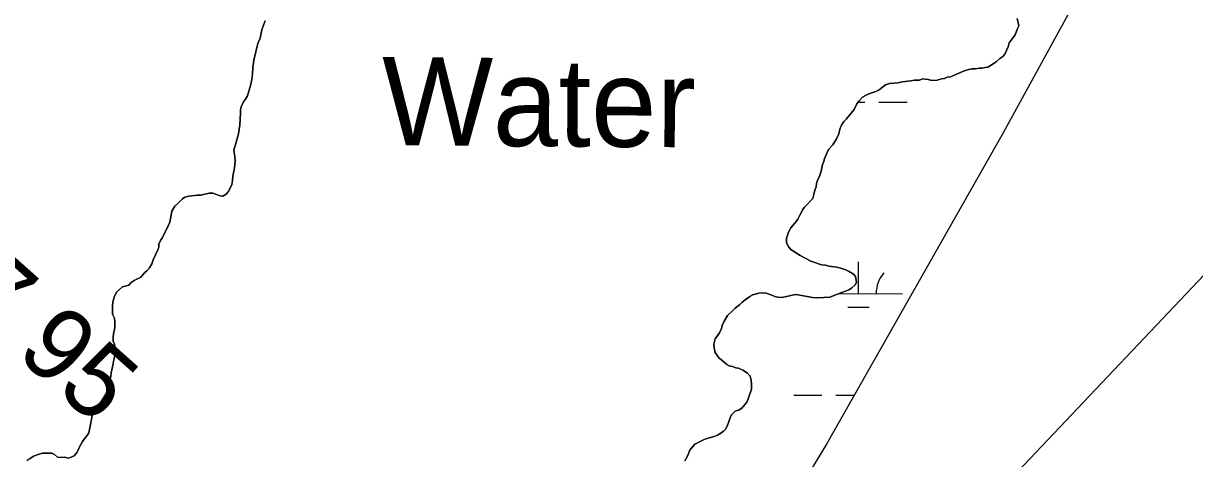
# Model space of a CAD drawing. Extents: x 3172297 to 3210190, y 958463 to 983887.
# Drawn here: x 3192826 to 3194156, y 965801 to 966296 of the extents above; entities that cross this region are included whole.
import ezdxf

# ---------------------------------------------------------------- set-up
doc = ezdxf.new("R2010")
doc.units = 0
for name, color, linetype in [('V-RIVR-IDEN', 7, 'Continuous'), ('V-RIVR-RANG-IDEN', 7, 'Continuous'), ('V-SITE-VEGE', 7, 'Continuous'), ('V-TOPO-MINR', 7, 'Continuous'), ('V-TOPO-SHOR', 7, 'Continuous'), ('V-WETL-SWMP', 7, 'Continuous')]:
    doc.layers.add(name, color=color, linetype=linetype)

msp = doc.modelspace()

# ---------------------------------------------------------------- linework, layer by layer
at = {"layer": 'V-SITE-VEGE'}
for p, q in [((3193098.4, 966293.5), (3193100.5, 966298.7)), ((3193955, 966301.1), (3193956.8, 966292.8)), ((3193095.4, 966282.8), (3193096.7, 966288.3)), ((3193096.7, 966288.3), (3193098.4, 966293.5)), ((3193955.1, 966289.7), (3193952.7, 966282.8)), ((3193956.8, 966292.8), (3193955.1, 966289.7)), ((3193087.5, 966253.8), (3193091.9, 966272.8)), ((3193091.9, 966272.8), (3193094.7, 966278.7)), ((3193094.7, 966278.7), (3193095.4, 966282.8)), ((3193945.8, 966273.5), (3193944.5, 966269)), ((3193952.7, 966282.8), (3193945.8, 966273.5)), ((3193941, 966260.8), (3193938.6, 966258)), ((3193944.5, 966269), (3193941, 966260.8)), ((3193085.9, 966238), (3193086.2, 966245.6)), ((3193086.2, 966245.6), (3193086.9, 966250.7)), ((3193086.9, 966250.7), (3193087.5, 966253.8)), ((3193918.4, 966245.5), (3193914.9, 966244.8)), ((3193921.5, 966245.9), (3193918.4, 966245.5)), ((3193927.6, 966249.7), (3193921.5, 966245.9)), ((3193931.1, 966252.1), (3193927.6, 966249.7)), ((3193935.2, 966255.6), (3193931.1, 966252.1)), ((3193938.6, 966258), (3193935.2, 966255.6)), ((3193083.8, 966225.2), (3193085.2, 966232.1)), ((3193085.2, 966232.1), (3193085.9, 966238)), ((3193847.1, 966232.5), (3193843.7, 966231.2)), ((3193853.6, 966231.9), (3193847.1, 966232.5)), ((3193857.8, 966230.9), (3193853.6, 966231.9)), ((3193868.8, 966232.6), (3193864, 966231.2)), ((3193872.2, 966233), (3193868.8, 966232.6)), ((3193875.3, 966234.4), (3193872.2, 966233)), ((3193879.1, 966235.1), (3193875.3, 966234.4)), ((3193893.9, 966241.3), (3193879.1, 966235.1)), ((3193898.4, 966243), (3193893.9, 966241.3)), ((3193903.5, 966244.1), (3193898.4, 966243)), ((3193907.7, 966244.1), (3193903.5, 966244.1)), ((3193911.8, 966244.8), (3193907.7, 966244.1)), ((3193914.9, 966244.8), (3193911.8, 966244.8)), ((3193080.1, 966213.5), (3193083.8, 966225.2)), ((3193797.9, 966220.3), (3193794.4, 966218.3)), ((3193805.4, 966225.9), (3193797.9, 966220.3)), ((3193809.6, 966227.3), (3193805.4, 966225.9)), ((3193819.6, 966228.3), (3193809.6, 966227.3)), ((3193824, 966229.4), (3193819.6, 966228.3)), ((3193834, 966230.4), (3193824, 966229.4)), ((3193838.1, 966231.1), (3193834, 966230.4)), ((3193843.7, 966231.2), (3193838.1, 966231.1)), ((3193864, 966231.2), (3193857.8, 966230.9)), ((3193073.2, 966200.8), (3193075.6, 966206.6)), ((3193075.6, 966206.6), (3193078, 966209.7)), ((3193078, 966209.7), (3193080.1, 966213.5)), ((3193774.8, 966207.5), (3193772.4, 966203.4)), ((3193779, 966211.7), (3193774.8, 966207.5)), ((3193782.4, 966213.7), (3193779, 966211.7)), ((3193786.2, 966215.5), (3193782.4, 966213.7)), ((3193794.4, 966218.3), (3193786.2, 966215.5)), ((3193071.6, 966180.1), (3193072.2, 966194.2)), ((3193072.2, 966197.3), (3193073.2, 966200.8)), ((3193072.2, 966194.2), (3193072.2, 966197.3)), ((3193769.7, 966197.8), (3193760.8, 966187.1)), ((3193772.4, 966203.4), (3193769.7, 966197.8)), ((3193069.9, 966170.4), (3193071.6, 966180.1)), ((3193755.3, 966179.9), (3193753.2, 966175.4)), ((3193758, 966184.4), (3193755.3, 966179.9)), ((3193760.8, 966187.1), (3193758, 966184.4)), ((3193067.5, 966160.8), (3193069.9, 966170.4)), ((3193752.2, 966170.2), (3193749.5, 966164.4)), ((3193753.2, 966175.4), (3193752.2, 966170.2)), ((3193064.8, 966151.5), (3193067.5, 966160.8)), ((3193740.6, 966152.6), (3193735.8, 966142.3)), ((3193745.4, 966157.8), (3193740.6, 966152.6)), ((3193749.5, 966164.4), (3193745.4, 966157.8)), ((3193065.8, 966144.2), (3193064.8, 966151.5)), ((3193065.5, 966131.8), (3193066.2, 966139.4)), ((3193066.2, 966139.4), (3193065.8, 966144.2)), ((3193735.1, 966138.8), (3193733.7, 966135.4)), ((3193735.8, 966142.3), (3193735.1, 966138.8)), ((3193063.5, 966122.2), (3193065.5, 966131.8)), ((3193732, 966127.8), (3193729.7, 966120.9)), ((3193733.7, 966135.4), (3193732, 966127.8)), ((3193058.7, 966104.6), (3193062.5, 966112.5)), ((3193062.5, 966112.5), (3193063.2, 966117.4)), ((3193063.2, 966117.4), (3193063.5, 966122.2)), ((3193726.9, 966114), (3193726.3, 966109.9)), ((3193728.3, 966118.2), (3193726.9, 966114)), ((3193729.7, 966120.9), (3193728.3, 966118.2)), ((3193009.2, 966098.2), (3193013.6, 966099.3)), ((3193013.6, 966099.3), (3193022.9, 966100.4)), ((3193022.9, 966100.4), (3193027.4, 966100.7)), ((3193027.4, 966100.7), (3193036.7, 966102.8)), ((3193036.7, 966102.8), (3193040.8, 966102.8)), ((3193040.8, 966102.8), (3193049.1, 966099.8)), ((3193049.1, 966099.8), (3193052.2, 966099.4)), ((3193052.2, 966099.4), (3193056, 966101.8)), ((3193056, 966101.8), (3193058.7, 966104.6)), ((3193723.9, 966101.3), (3193722.5, 966096.8)), ((3193724.9, 966106.1), (3193723.9, 966101.3)), ((3193726.3, 966109.9), (3193724.9, 966106.1)), ((3192994.4, 966082.4), (3192997.8, 966088.2)), ((3192997.8, 966088.2), (3193002.3, 966092.4)), ((3193002.3, 966092.4), (3193006.4, 966096.5)), ((3193006.4, 966096.5), (3193009.2, 966098.2)), ((3193713.2, 966086.8), (3193711.2, 966084.3)), ((3193722.5, 966096.8), (3193713.2, 966086.8)), ((3192992, 966069.9), (3192993, 966075.8)), ((3192993, 966075.8), (3192994.4, 966082.4)), ((3193705.7, 966073.3), (3193703.6, 966070.5)), ((3193707.8, 966077.8), (3193705.7, 966073.3)), ((3193711.2, 966084.3), (3193707.8, 966077.8)), ((3192983.5, 966052.4), (3192986.6, 966058.9)), ((3192986.6, 966058.9), (3192988.6, 966062.4)), ((3192988.6, 966062.4), (3192990.3, 966065.8)), ((3192990.3, 966065.8), (3192992, 966069.9)), ((3193697.5, 966063.3), (3193695.1, 966058.5)), ((3193703.6, 966070.5), (3193697.5, 966063.3)), ((3192979.7, 966044.8), (3192981.4, 966049.2)), ((3192981.4, 966049.2), (3192983.5, 966052.4)), ((3193693.7, 966055), (3193692.7, 966051.6)), ((3193692.7, 966051.6), (3193692.7, 966046.4)), ((3193692.7, 966046.4), (3193695.5, 966041.6)), ((3193695.1, 966058.5), (3193693.7, 966055)), ((3192973.2, 966027.2), (3192978.4, 966038.6)), ((3192978.4, 966038.6), (3192979.4, 966041.7)), ((3192979.4, 966041.7), (3192979.7, 966044.8)), ((3193695.5, 966041.6), (3193697.5, 966038.8)), ((3193697.5, 966038.8), (3193702, 966036.1)), ((3193702, 966036.1), (3193708.2, 966032)), ((3192969.1, 966018.2), (3192971.5, 966022.7)), ((3192971.5, 966022.7), (3192973.2, 966027.2)), ((3193708.2, 966032), (3193720.3, 966025.8)), ((3193720.3, 966025.8), (3193723.8, 966024.4)), ((3193723.8, 966024.4), (3193732.7, 966021.4)), ((3193732.7, 966021.4), (3193736.9, 966021)), ((3193736.9, 966021), (3193741, 966020)), ((3193741, 966020), (3193750, 966018.7)), ((3192954.7, 966005.1), (3192958.5, 966007.1)), ((3192958.5, 966007.1), (3192960.9, 966009.9)), ((3192960.9, 966009.9), (3192963.6, 966012.7)), ((3192963.6, 966012.7), (3192966, 966014.8)), ((3192966, 966014.8), (3192969.1, 966018.2)), ((3193750, 966018.7), (3193755.8, 966017.3)), ((3193755.8, 966017.3), (3193760.3, 966015.6)), ((3193760.3, 966015.6), (3193763.1, 966014.2)), ((3193763.1, 966014.2), (3193768.9, 966010.8)), ((3193768.9, 966010.8), (3193771, 966008.1)), ((3193771, 966008.1), (3193772.4, 966001.9)), ((3192931.7, 965990.9), (3192938.2, 965996.4)), ((3192938.2, 965996.4), (3192941.3, 965997.1)), ((3192941.3, 965997.1), (3192945.4, 965998.5)), ((3192945.4, 965998.5), (3192948.2, 966001.3)), ((3192948.2, 966001.3), (3192951.6, 966003.7)), ((3192951.6, 966003.7), (3192954.7, 966005.1)), ((3193763.5, 965993.2), (3193759.7, 965991.5)), ((3193766.6, 965995), (3193763.5, 965993.2)), ((3193771, 965999.1), (3193766.6, 965995)), ((3193772.4, 966001.9), (3193771, 965999.1)), ((3192927.2, 965978.5), (3192928.6, 965985)), ((3192928.6, 965985), (3192931.7, 965990.9)), ((3193645.7, 965981.8), (3193641.9, 965978.7)), ((3193650.9, 965985.6), (3193645.7, 965981.8)), ((3193653.6, 965987), (3193650.9, 965985.6)), ((3193654, 965987.4), (3193653.6, 965987)), ((3193661.2, 965989.1), (3193654, 965987.4)), ((3193665, 965989.5), (3193661.2, 965989.1)), ((3193669.8, 965989.1), (3193665, 965989.5)), ((3193676, 965987.1), (3193669.8, 965989.1)), ((3193679.5, 965985.4), (3193676, 965987.1)), ((3193682.9, 965984.7), (3193679.5, 965985.4)), ((3193687.4, 965984.4), (3193682.9, 965984.7)), ((3193691.2, 965985.1), (3193687.4, 965984.4)), ((3193697.7, 965986.8), (3193691.2, 965985.1)), ((3193702.5, 965987.9), (3193697.7, 965986.8)), ((3193705.6, 965987.5), (3193702.5, 965987.9)), ((3193712.2, 965986.2), (3193705.6, 965987.5)), ((3193722.2, 965984.5), (3193712.2, 965986.2)), ((3193727.7, 965983.8), (3193722.2, 965984.5)), ((3193735.3, 965984.2), (3193727.7, 965983.8)), ((3193741.8, 965984.9), (3193735.3, 965984.2)), ((3193750.8, 965988), (3193741.8, 965984.9)), ((3193755.6, 965990.1), (3193750.8, 965988)), ((3193759.7, 965991.5), (3193755.6, 965990.1)), ((3192926.9, 965975.4), (3192927.2, 965978.5)), ((3192926.9, 965965.4), (3192926.9, 965975.4)), ((3193631, 965969), (3193625.8, 965963.8)), ((3193634.4, 965972.1), (3193631, 965969)), ((3193639.2, 965975.9), (3193634.4, 965972.1)), ((3193641.9, 965978.7), (3193639.2, 965975.9)), ((3192929.3, 965960.9), (3192926.9, 965965.4)), ((3192929.7, 965956.4), (3192929.3, 965960.9)), ((3192929.4, 965950.2), (3192929.7, 965956.4)), ((3193619.6, 965952.5), (3193619, 965949)), ((3193621.7, 965956.6), (3193619.6, 965952.5)), ((3193625.8, 965963.8), (3193621.7, 965956.6)), ((3192927.7, 965938.8), (3192928, 965943)), ((3192927.7, 965934.7), (3192927.7, 965938.8)), ((3192928, 965943), (3192929.4, 965950.2)), ((3193616.6, 965944.2), (3193611.8, 965937.3)), ((3193619, 965949), (3193616.6, 965944.2)), ((3192929.1, 965931.3), (3192927.7, 965934.7)), ((3192929.5, 965928.2), (3192929.1, 965931.3)), ((3192929.8, 965921.3), (3192929.5, 965928.2)), ((3193611.8, 965937.3), (3193610.1, 965931.4)), ((3193610.1, 965931.4), (3193610.4, 965927.3)), ((3193610.4, 965927.3), (3193611.8, 965921.8)), ((3192928.1, 965912), (3192928.8, 965915.1)), ((3192928.8, 965915.1), (3192929.8, 965921.3)), ((3193611.8, 965921.8), (3193616.3, 965915.3)), ((3193616.3, 965915.3), (3193619.1, 965913.2)), ((3193619.1, 965913.2), (3193621.8, 965910.8)), ((3192925.4, 965898.9), (3192927.8, 965908.9)), ((3192927.8, 965908.9), (3192928.1, 965912)), ((3193621.8, 965910.8), (3193625, 965908.4)), ((3193625, 965908.4), (3193627.7, 965906.7)), ((3193627.7, 965906.7), (3193631.2, 965906)), ((3193631.2, 965906), (3193635, 965904.6)), ((3193635, 965904.6), (3193638.1, 965904)), ((3193638.1, 965904), (3193643.2, 965901.9)), ((3193643.2, 965901.9), (3193648.4, 965898.5)), ((3192923.1, 965885.1), (3192923.7, 965889.6)), ((3192923.7, 965889.6), (3192925.1, 965895.1)), ((3192925.1, 965895.1), (3192925.4, 965898.9)), ((3193648.4, 965898.5), (3193651.5, 965895)), ((3193651.5, 965895), (3193652.6, 965890.6)), ((3193652.6, 965890.6), (3193652.9, 965885.7)), ((3193652.9, 965885.7), (3193652.9, 965880.2)), ((3192914.5, 965866.8), (3192919.3, 965874.4)), ((3192919.3, 965874.4), (3192922, 965879.9)), ((3192922, 965879.9), (3192923.1, 965885.1)), ((3193652.9, 965880.2), (3193649.2, 965869.2)), ((3192907.6, 965857.8), (3192911.8, 965862.7)), ((3192911.8, 965862.7), (3192914.5, 965866.8)), ((3193647.5, 965865.4), (3193642, 965858.5)), ((3193649.2, 965869.2), (3193647.5, 965865.4)), ((3192901.8, 965840.3), (3192902.9, 965846.1)), ((3192902.9, 965846.1), (3192903.9, 965850.2)), ((3192903.9, 965850.2), (3192905.2, 965853.4)), ((3192905.2, 965853.4), (3192907.6, 965857.8)), ((3193628.6, 965847.8), (3193625.5, 965838.1)), ((3193630.3, 965851.2), (3193628.6, 965847.8)), ((3193634.4, 965855.4), (3193630.3, 965851.2)), ((3193638.9, 965856.8), (3193634.4, 965855.4)), ((3193642, 965858.5), (3193638.9, 965856.8)), ((3192899.8, 965830.6), (3192901.8, 965840.3)), ((3193621.1, 965832.6), (3193618, 965830.2)), ((3193623.5, 965835), (3193621.1, 965832.6)), ((3193625.5, 965838.1), (3193623.5, 965835)), ((3192890.9, 965817.5), (3192892.6, 965820.9)), ((3192892.6, 965820.9), (3192895.7, 965825.1)), ((3192895.7, 965825.1), (3192898.1, 965827.5)), ((3192898.1, 965827.5), (3192899.8, 965830.6)), ((3193597.7, 965822.5), (3193588.7, 965817.7)), ((3193601.1, 965823.9), (3193597.7, 965822.5)), ((3193610.4, 965826.4), (3193601.1, 965823.9)), ((3193614.5, 965828.1), (3193610.4, 965826.4)), ((3193618, 965830.2), (3193614.5, 965828.1)), ((3192837.2, 965804.2), (3192842.4, 965806)), ((3192842.4, 965806), (3192847.5, 965807.4)), ((3192847.5, 965807.4), (3192852.7, 965807.7)), ((3192852.7, 965807.7), (3192857.5, 965807.4)), ((3192857.5, 965807.4), (3192861, 965806)), ((3192861, 965806), (3192864.4, 965802.9)), ((3192883.4, 965804.7), (3192885.8, 965807.5)), ((3192885.8, 965807.5), (3192887.8, 965810.9)), ((3192887.8, 965810.9), (3192889.2, 965814.7)), ((3192889.2, 965814.7), (3192890.9, 965817.5)), ((3193582.9, 965810.8), (3193580.2, 965804.2)), ((3193586.3, 965815.3), (3193582.9, 965810.8)), ((3193588.7, 965817.7), (3193586.3, 965815.3)), ((3192833.4, 965801.5), (3192837.2, 965804.2)), ((3192864.4, 965802.9), (3192868.2, 965802.6)), ((3192868.2, 965802.6), (3192872.3, 965803)), ((3192872.3, 965803), (3192876.8, 965801.9)), ((3192876.8, 965801.9), (3192880.6, 965803.3)), ((3192880.6, 965803.3), (3192883.4, 965804.7)), ((3193580.2, 965804.2), (3193577.1, 965799))]:
    msp.add_line(p, q, dxfattribs=at)
at = {"layer": 'V-TOPO-MINR'}
msp.add_lwpolyline([(3194372.2, 966226.2), (3193580, 965390.5)], dxfattribs=at)
at = {"layer": 'V-TOPO-SHOR'}
for points in [[(3193100.5, 966298.7), (3193098.4, 966293.5), (3193096.7, 966288.3), (3193095.4, 966282.8), (3193094.7, 966278.7), (3193091.9, 966272.8), (3193087.5, 966253.8), (3193086.9, 966250.7), (3193086.2, 966245.6), (3193085.9, 966238), (3193085.2, 966232.1), (3193083.8, 966225.2), (3193080.1, 966213.5), (3193078, 966209.7), (3193075.6, 966206.6), (3193073.2, 966200.8), (3193072.2, 966197.3), (3193072.2, 966194.2), (3193071.6, 966180.1), (3193069.9, 966170.4), (3193067.5, 966160.8), (3193064.8, 966151.5), (3193065.8, 966144.2), (3193066.2, 966139.4), (3193065.5, 966131.8), (3193063.5, 966122.2), (3193063.2, 966117.4), (3193062.5, 966112.5), (3193058.7, 966104.6), (3193056, 966101.8), (3193052.2, 966099.4), (3193049.1, 966099.8), (3193040.8, 966102.8), (3193036.7, 966102.8), (3193027.4, 966100.7), (3193022.9, 966100.4), (3193013.6, 966099.3), (3193009.2, 966098.2), (3193006.4, 966096.5), (3193002.3, 966092.4), (3192997.8, 966088.2), (3192994.4, 966082.4), (3192993, 966075.8), (3192992, 966069.9), (3192990.3, 966065.8), (3192988.6, 966062.4), (3192986.6, 966058.9), (3192983.5, 966052.4), (3192981.4, 966049.2), (3192979.7, 966044.8), (3192979.4, 966041.7), (3192978.4, 966038.6), (3192973.2, 966027.2), (3192971.5, 966022.7), (3192969.1, 966018.2), (3192966, 966014.8), (3192963.6, 966012.7), (3192960.9, 966009.9), (3192958.5, 966007.1), (3192954.7, 966005.1), (3192951.6, 966003.7), (3192948.2, 966001.3), (3192945.4, 965998.5), (3192941.3, 965997.1), (3192938.2, 965996.4), (3192931.7, 965990.9), (3192928.6, 965985), (3192927.2, 965978.5), (3192926.9, 965975.4), (3192926.9, 965965.4), (3192929.3, 965960.9), (3192929.7, 965956.4), (3192929.4, 965950.2)], [(3193749.5, 966164.4), (3193752.2, 966170.2), (3193753.2, 966175.4), (3193755.3, 966179.9), (3193758, 966184.4), (3193760.8, 966187.1), (3193769.7, 966197.8), (3193772.4, 966203.4), (3193774.8, 966207.5), (3193779, 966211.7), (3193782.4, 966213.7), (3193786.2, 966215.5), (3193794.4, 966218.3), (3193797.9, 966220.3), (3193805.4, 966225.9), (3193809.6, 966227.3), (3193819.6, 966228.3), (3193824, 966229.4), (3193834, 966230.4), (3193838.1, 966231.1), (3193843.7, 966231.2), (3193847.1, 966232.5), (3193853.6, 966231.9), (3193857.8, 966230.9), (3193864, 966231.2), (3193868.8, 966232.6), (3193872.2, 966233), (3193875.3, 966234.4), (3193879.1, 966235.1), (3193893.9, 966241.3), (3193898.4, 966243), (3193903.5, 966244.1), (3193907.7, 966244.1), (3193911.8, 966244.8), (3193914.9, 966244.8), (3193918.4, 966245.5), (3193921.5, 966245.9), (3193927.6, 966249.7), (3193931.1, 966252.1), (3193935.2, 966255.6), (3193938.6, 966258), (3193941, 966260.8), (3193944.5, 966269), (3193945.8, 966273.5), (3193952.7, 966282.8), (3193955.1, 966289.7), (3193956.8, 966292.8), (3193955, 966301.1)], [(3193625.5, 965838.1), (3193628.6, 965847.8), (3193630.3, 965851.2), (3193634.4, 965855.4), (3193638.9, 965856.8), (3193642, 965858.5), (3193647.5, 965865.4), (3193649.2, 965869.2), (3193652.9, 965880.2), (3193652.9, 965885.7), (3193652.6, 965890.6), (3193651.5, 965895), (3193648.4, 965898.5), (3193643.2, 965901.9), (3193638.1, 965904), (3193635, 965904.6), (3193631.2, 965906), (3193627.7, 965906.7), (3193625, 965908.4), (3193621.8, 965910.8), (3193619.1, 965913.2), (3193616.3, 965915.3), (3193611.8, 965921.8), (3193610.4, 965927.3), (3193610.1, 965931.4), (3193611.8, 965937.3), (3193616.6, 965944.2), (3193619, 965949), (3193619.6, 965952.5), (3193621.7, 965956.6), (3193625.8, 965963.8), (3193631, 965969), (3193634.4, 965972.1), (3193639.2, 965975.9), (3193641.9, 965978.7), (3193645.7, 965981.8), (3193650.9, 965985.6), (3193653.6, 965987), (3193654, 965987.4), (3193661.2, 965989.1), (3193665, 965989.5), (3193669.8, 965989.1), (3193676, 965987.1), (3193679.5, 965985.4), (3193682.9, 965984.7), (3193687.4, 965984.4), (3193691.2, 965985.1), (3193697.7, 965986.8), (3193702.5, 965987.9), (3193705.6, 965987.5), (3193712.2, 965986.2), (3193722.2, 965984.5), (3193727.7, 965983.8), (3193735.3, 965984.2), (3193741.8, 965984.9), (3193750.8, 965988), (3193755.6, 965990.1), (3193759.7, 965991.5), (3193763.5, 965993.2), (3193766.6, 965995), (3193771, 965999.1), (3193772.4, 966001.9), (3193771, 966008.1), (3193768.9, 966010.8), (3193763.1, 966014.2), (3193760.3, 966015.6), (3193755.8, 966017.3), (3193750, 966018.7), (3193741, 966020), (3193736.9, 966021), (3193732.7, 966021.4), (3193723.8, 966024.4), (3193720.3, 966025.8), (3193708.2, 966032), (3193702, 966036.1), (3193697.5, 966038.8), (3193695.5, 966041.6), (3193692.7, 966046.4), (3193692.7, 966051.6), (3193693.7, 966055), (3193695.1, 966058.5), (3193697.5, 966063.3), (3193703.6, 966070.5), (3193705.7, 966073.3), (3193707.8, 966077.8), (3193711.2, 966084.3), (3193713.2, 966086.8), (3193722.5, 966096.8), (3193723.9, 966101.3), (3193724.9, 966106.1), (3193726.3, 966109.9), (3193726.9, 966114), (3193728.3, 966118.2), (3193729.7, 966120.9), (3193732, 966127.8), (3193733.7, 966135.4), (3193735.1, 966138.8), (3193735.8, 966142.3), (3193740.6, 966152.6), (3193745.4, 966157.8), (3193749.5, 966164.4)], [(3192929.4, 965950.2), (3192928, 965943), (3192927.7, 965938.8), (3192927.7, 965934.7), (3192929.1, 965931.3), (3192929.5, 965928.2), (3192929.8, 965921.3), (3192928.8, 965915.1), (3192928.1, 965912), (3192927.8, 965908.9), (3192925.4, 965898.9), (3192925.1, 965895.1), (3192923.7, 965889.6), (3192923.1, 965885.1), (3192922, 965879.9), (3192919.3, 965874.4), (3192914.5, 965866.8), (3192911.8, 965862.7), (3192907.6, 965857.8), (3192905.2, 965853.4), (3192903.9, 965850.2), (3192902.9, 965846.1), (3192901.8, 965840.3), (3192899.8, 965830.6), (3192898.1, 965827.5), (3192895.7, 965825.1), (3192892.6, 965820.9), (3192890.9, 965817.5), (3192889.2, 965814.7), (3192887.8, 965810.9), (3192885.8, 965807.5), (3192883.4, 965804.7), (3192880.6, 965803.3), (3192876.8, 965801.9), (3192872.3, 965803), (3192868.2, 965802.6), (3192864.4, 965802.9), (3192861, 965806), (3192857.5, 965807.4), (3192852.7, 965807.7), (3192847.5, 965807.4), (3192842.4, 965806), (3192837.2, 965804.2), (3192833.4, 965801.5), (3192829.6, 965799)], [(3193577.1, 965799), (3193580.2, 965804.2), (3193582.9, 965810.8), (3193586.3, 965815.3), (3193588.7, 965817.7), (3193597.7, 965822.5), (3193601.1, 965823.9), (3193610.4, 965826.4), (3193614.5, 965828.1), (3193618, 965830.2), (3193621.1, 965832.6), (3193623.5, 965835), (3193625.5, 965838.1)]]:
    msp.add_lwpolyline(points, dxfattribs=at)
at = {"layer": 'V-WETL-SWMP'}
for p, q in [((3193774, 966206.1), (3193781.8, 966206.1)), ((3193797.8, 966206), (3193829.8, 966206)), ((3193774.6, 965988.8), (3193774.7, 966024.8)), ((3193752.8, 965988.9), (3193824.6, 965988.7)), ((3193762.6, 965973.4), (3193786.6, 965973.4)), ((3193700.9, 965873.6), (3193732.9, 965873.5)), ((3193748.9, 965873.5), (3193769.8, 965873.4))]:
    msp.add_line(p, q, dxfattribs=at)
for points in [[(3194157.1, 966530.4), (3194103, 966447), (3194059.6, 966392), (3194048.8, 966371.8), (3193939, 966171.2), (3193738.1, 965817.7), (3193624.5, 965630.7)], [(3193749.5, 966164.4), (3193752.2, 966170.2), (3193753.2, 966175.4), (3193755.3, 966179.9), (3193758, 966184.4), (3193760.8, 966187.1), (3193769.7, 966197.8), (3193772.4, 966203.4), (3193774.8, 966207.5), (3193779, 966211.7), (3193782.4, 966213.7), (3193786.2, 966215.5), (3193794.4, 966218.3), (3193797.9, 966220.3), (3193805.4, 966225.9), (3193809.6, 966227.3), (3193819.6, 966228.3), (3193824, 966229.4), (3193834, 966230.4), (3193838.1, 966231.1), (3193843.7, 966231.2), (3193847.1, 966232.5), (3193853.6, 966231.9), (3193857.8, 966230.9), (3193864, 966231.2), (3193868.8, 966232.6), (3193872.2, 966233), (3193875.3, 966234.4), (3193879.1, 966235.1), (3193893.9, 966241.3), (3193898.4, 966243), (3193903.5, 966244.1), (3193907.7, 966244.1), (3193911.8, 966244.8), (3193914.9, 966244.8), (3193918.4, 966245.5), (3193921.5, 966245.9), (3193927.6, 966249.7), (3193931.1, 966252.1), (3193935.2, 966255.6), (3193938.6, 966258), (3193941, 966260.8), (3193944.5, 966269), (3193945.8, 966273.5), (3193952.7, 966282.8), (3193955.1, 966289.7), (3193956.8, 966292.8), (3193955, 966301.1)], [(3193625.5, 965838.1), (3193628.6, 965847.8), (3193630.3, 965851.2), (3193634.4, 965855.4), (3193638.9, 965856.8), (3193642, 965858.5), (3193647.5, 965865.4), (3193649.2, 965869.2), (3193652.9, 965880.2), (3193652.9, 965885.7), (3193652.6, 965890.6), (3193651.5, 965895), (3193648.4, 965898.5), (3193643.2, 965901.9), (3193638.1, 965904), (3193635, 965904.6), (3193631.2, 965906), (3193627.7, 965906.7), (3193625, 965908.4), (3193621.8, 965910.8), (3193619.1, 965913.2), (3193616.3, 965915.3), (3193611.8, 965921.8), (3193610.4, 965927.3), (3193610.1, 965931.4), (3193611.8, 965937.3), (3193616.6, 965944.2), (3193619, 965949), (3193619.6, 965952.5), (3193621.7, 965956.6), (3193625.8, 965963.8), (3193631, 965969), (3193634.4, 965972.1), (3193639.2, 965975.9), (3193641.9, 965978.7), (3193645.7, 965981.8), (3193650.9, 965985.6), (3193653.6, 965987), (3193654, 965987.4), (3193661.2, 965989.1), (3193665, 965989.5), (3193669.8, 965989.1), (3193676, 965987.1), (3193679.5, 965985.4), (3193682.9, 965984.7), (3193687.4, 965984.4), (3193691.2, 965985.1), (3193697.7, 965986.8), (3193702.5, 965987.9), (3193705.6, 965987.5), (3193712.2, 965986.2), (3193722.2, 965984.5), (3193727.7, 965983.8), (3193735.3, 965984.2), (3193741.8, 965984.9), (3193750.8, 965988), (3193755.6, 965990.1), (3193759.7, 965991.5), (3193763.5, 965993.2), (3193766.6, 965995), (3193771, 965999.1), (3193772.4, 966001.9), (3193771, 966008.1), (3193768.9, 966010.8), (3193763.1, 966014.2), (3193760.3, 966015.6), (3193755.8, 966017.3), (3193750, 966018.7), (3193741, 966020), (3193736.9, 966021), (3193732.7, 966021.4), (3193723.8, 966024.4), (3193720.3, 966025.8), (3193708.2, 966032), (3193702, 966036.1), (3193697.5, 966038.8), (3193695.5, 966041.6), (3193692.7, 966046.4), (3193692.7, 966051.6), (3193693.7, 966055), (3193695.1, 966058.5), (3193697.5, 966063.3), (3193703.6, 966070.5), (3193705.7, 966073.3), (3193707.8, 966077.8), (3193711.2, 966084.3), (3193713.2, 966086.8), (3193722.5, 966096.8), (3193723.9, 966101.3), (3193724.9, 966106.1), (3193726.3, 966109.9), (3193726.9, 966114), (3193728.3, 966118.1), (3193729.7, 966120.9), (3193732, 966127.8), (3193733.7, 966135.4), (3193735.1, 966138.8), (3193735.8, 966142.3), (3193740.6, 966152.6), (3193745.4, 966157.8), (3193749.5, 966164.4)], [(3193577.1, 965799), (3193580.2, 965804.2), (3193582.9, 965810.8), (3193586.3, 965815.3), (3193588.7, 965817.7), (3193597.7, 965822.5), (3193601.1, 965823.9), (3193610.4, 965826.4), (3193614.5, 965828.1), (3193618, 965830.2), (3193621.1, 965832.6), (3193623.5, 965835), (3193625.5, 965838.1)]]:
    msp.add_lwpolyline(points, dxfattribs=at)
for centre, start, end in [((3193829.9, 965989.2), 139.0865, 180.6302), ((3193719.4, 965989.5), 359.0865, 0.4018)]:
    msp.add_arc(centre, 35.2, start, end, dxfattribs=at)

# ---------------------------------------------------------------- texts
at = {"layer": 'V-RIVR-IDEN'}
msp.add_text('Water', height=100, rotation=359.5938, dxfattribs=at).set_placement((3193232.6, 966157.4))
at = {"layer": 'V-RIVR-RANG-IDEN'}
msp.add_text('R-317.95', height=83, rotation=318.3939, dxfattribs=at).set_placement((3192566.3, 966140.9))

doc.saveas('drawing.dxf')
